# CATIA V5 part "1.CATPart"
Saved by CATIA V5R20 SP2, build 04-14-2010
Part number: 1
Bounding box of the stored display mesh (mm): x -200 to 200, y -500 to 500, z -25 to 420
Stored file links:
  C:\Users\Orange\Desktop\Assembly Design-14\1.CATPart
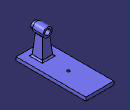
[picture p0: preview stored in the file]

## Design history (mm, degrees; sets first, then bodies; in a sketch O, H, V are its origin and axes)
Body1 (main body)
  Sketch1 on xy-plane, origin (0, 0, 0), H (1, 0, 0), V (0, 1, 0)
    line L1 (200, 500) -> (-200, 500)
    line L2 (-200, 500) -> (-200, -500)
    line L3 (-200, -500) -> (200, -500)
    line L4 (200, -500) -> (200, 500)
  Pad1: profile Sketch1, direction (0, 0, 1), length 25, mirrored extent
  Sketch2 on face of Pad1 from Sketch1.L3, origin (0, -500, 0), H (1, 0, 0), V (0, 0, 1)
    line L1 (75, 25) -> (-75, 25)
    point P4 (-50, 313.4669)
    line L2 (50, 313.4669) -> (75, 25)
    line L3 (-50, 313.4669) -> (-75, 25)
    arc A1 centre (0, 355) radius 65 from (-50, 313.4669) to (50, 313.4669) ccw
    point P5 (-50, 313.4669)
    coincidence: P4 P5
  Sketch3 on face of Pad1 from Sketch1.L3, origin (0, -500, 0), H (1, 0, 0), V (0, 0, 1)
  Pad2: profile Sketch2, direction (0, 1, 0), length 250, opposite side length -100
  Sketch4 on yz-plane, origin (0, 0, 0), H (0, 1, 0), V (0, 0, 1)
    line L1 (-275, 313.4669) -> (-250, 25)
    line L2 (-250, 25) -> (-91.3436, 220.2832)
    line L3 (-91.3436, 220.2832) -> (-201.4054, 326.8319)
    line L4 (-201.4054, 326.8319) -> (-275, 313.4669)
    line L5 (-375, 313.4669) -> (-486.534, 350.1068)
    line L6 (-486.534, 350.1068) -> (-510.4095, 210.2551)
    line L7 (-510.4095, 210.2551) -> (-400, 25)
    line L8 (-400, 25) -> (-375, 313.4669)
  Pocket1: profile Sketch4, direction (-1, 0, 0), length 250, mirrored extent
  Sketch5 on face of Pad1 from Sketch1.L3, origin (0, -500, 0), H (1, 0, 0), V (0, 0, 1)
    circle A1 centre (0, 355) radius 65
    circle A2 centre (0, 355) radius 50
    circle A3 centre (0, 355) radius 40
  MultiPad1: profile Sketch5, domains (length 0; length 250 / length -60; length 250 / length -100)
  Fillet1: radius 20, on edge [face of MultiPad1 from Sketch5.A1 | face of Pad2 from Sketch2.L3]; edge [face of Pad2 from Sketch2.L3 | end face of Pad1]; edge [face of Pocket1 from Sketch4.L8 | end face of Pad1]; edge [end face of Pad1 | face of Pad2 from Sketch2.L2]; edge [end face of Pad1 | face of Pocket1 from Sketch4.L1]; edge [face of Pad2 from Sketch2.L2 | face of MultiPad1 from Sketch5.A1]
  Sketch6 on end face of Pad1, origin (0, 0, 25), H (1, 0, 0), V (0, 1, 0)
    circle A1 centre (0, 50) radius 20
  Pocket2: profile Sketch6, direction (0, 0, -1), length 250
